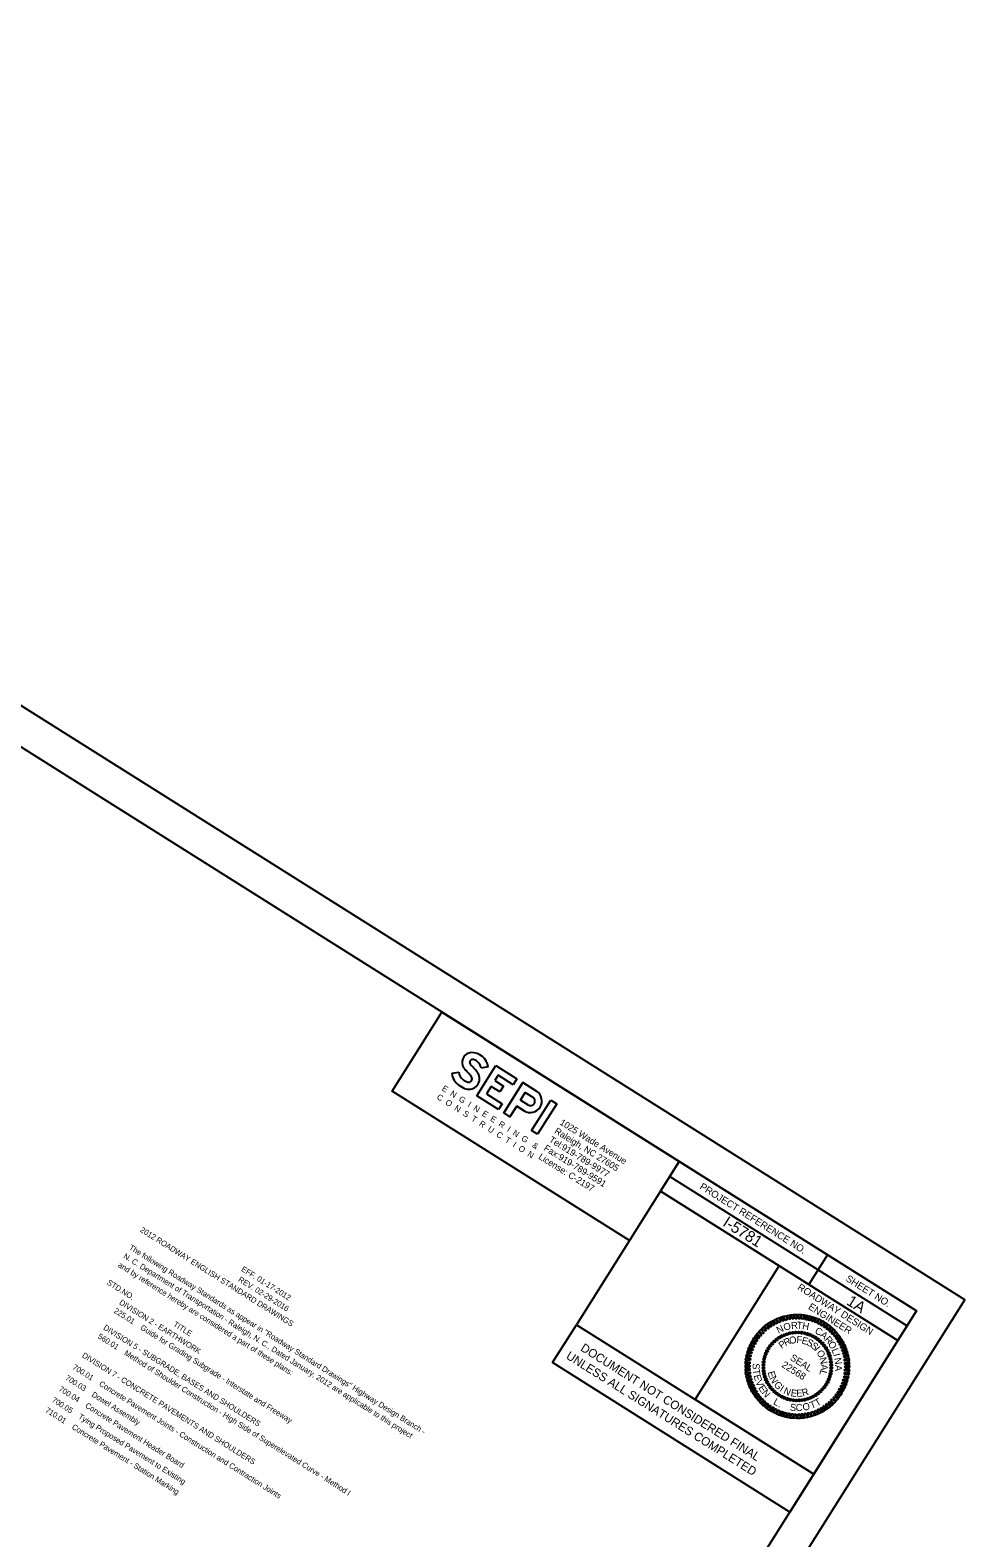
# Model space of a CAD drawing. Extents: x 2337281 to 2340318, y 809513 to 812268.
# Drawn here: x 2339318 to 2340318, y 810655 to 812268 of the extents above; entities that cross this region are included whole.
import ezdxf

# ---------------------------------------------------------------- set-up
doc = ezdxf.new("R2010")
doc.units = 0
for name, color, linetype in [('Default', 7, 'Continuous'), ('Old_Level_2', 7, 'Continuous'), ('Old_Level_58', 7, 'Continuous'), ('Old_Level_61', 7, 'Continuous'), ('Sheet Data Field CELL', 7, 'Continuous'), ('Sheet PE Seal Cell', 7, 'Continuous'), ('Sheet Plan And Profile CELL', 7, 'Continuous'), ('Sheet Plot Border Outside CELL', 7, 'Continuous'), ('Sheet Sticker Exception Certification CELL', 7, 'Continuous')]:
    doc.layers.add(name, color=color, linetype=linetype)

msp = doc.modelspace()

# ---------------------------------------------------------------- linework, layer by layer
at = {"layer": 'Old_Level_58'}
msp.add_lwpolyline([(2339758.7, 811217.1), (2340012.7, 811057.3), (2339959.4, 810972.6), (2339705.4, 811132.4)], close=True, dxfattribs=at)
at = {"layer": 'Old_Level_61'}
for p, q in [((2339769.5, 811151.6), (2339776.8, 811152.9)), ((2339796.1, 811127.4), (2339816.5, 811159.9)), ((2339808.3, 811158.6), (2339800.8, 811157)), ((2339819, 811149.5), (2339815.4, 811143.9)), ((2339816.5, 811159.9), (2339839, 811145.7)), ((2339835, 811139.3), (2339819, 811149.5)), ((2339811.5, 811137.6), (2339806.5, 811129.7)), ((2339820.8, 811131.7), (2339811.5, 811137.6)), ((2339815.4, 811143.9), (2339824.7, 811138)), ((2339824.7, 811138), (2339820.8, 811131.7)), ((2339839, 811145.7), (2339835, 811139.3)), ((2339860, 811132.5), (2339845.4, 811141.7)), ((2339819.3, 811112.8), (2339796.1, 811127.4)), ((2339806.5, 811129.7), (2339823.3, 811119.1)), ((2339823.3, 811119.1), (2339819.3, 811112.8)), ((2339850.8, 811117.8), (2339842.8, 811122.9)), ((2339854.7, 811090.5), (2339875.2, 811122.9)), ((2339881.6, 811118.9), (2339861.2, 811086.4)), ((2339875.2, 811122.9), (2339881.6, 811118.9)), ((2339861.2, 811086.4), (2339854.7, 811090.5))]:
    msp.add_line(p, q, dxfattribs=at)
for points in [[(2339846.8, 811111.5), (2339838.8, 811116.5), (2339831.6, 811105.1), (2339825, 811109.2), (2339845.4, 811141.7)], [(2339845.4, 811141.7), (2339825, 811109.2), (2339831.6, 811105.1), (2339838.8, 811116.5), (2339846.8, 811111.5)], [(2339842.8, 811122.9), (2339848, 811131.2), (2339856.1, 811126.2)], [(2339842.8, 811122.9), (2339848, 811131.2), (2339856.1, 811126.2)], [(2339845.4, 811141.7), (2339860, 811132.5)], [(2339850.8, 811117.8), (2339842.8, 811122.9)]]:
    msp.add_lwpolyline(points, dxfattribs=at)
for centre, radius, start, end in [((2339791, 811163.2), 10.6, 95.5503, 197.4787), ((2339791.7, 811163.3), 3.17, 71.3443, 183.3281), ((2339794.4, 811164.4), 6.07, 192.6469, 224.6621), ((2339790.3, 811155.4), 18.4, 9.946, 90.7914), ((2339789.3, 811155.1), 11.7, 9.434, 73.0111), ((2339786.2, 811152.9), 16.8, 184.1828, 236.8365), ((2339788.6, 811154.3), 11.9, 187.0277, 233.5862), ((2339795.3, 811165.8), 15.6, 201.8408, 225.1641), ((2339787.8, 811145.8), 11.3, 251.7121, 31.405), ((2339752.2, 811120.5), 47, 35.599, 46.8737), ((2339787.4, 811145.7), 3.69, 253.9268, 34.4617), ((2339754, 811121.2), 53.1, 35.0181, 47.1994), ((2339792.3, 811159.1), 25.4, 232.9472, 251.5878), ((2339790.8, 811156.4), 14.8, 231.6606, 252.8619), ((2339853.4, 811122), 12.4, 237.8219, 57.8219), ((2339853.4, 811122), 12.4, 237.8219, 57.8219), ((2339853.5, 811122), 4.93, 237.8219, 57.8219), ((2339853.5, 811122), 4.93, 237.8219, 57.8219)]:
    msp.add_arc(centre, radius, start, end, dxfattribs=at)
at = {"layer": 'Sheet PE Seal Cell'}
for points in [[(2340119.4, 810885), (2340117.3, 810889.2), (2340119.6, 810890.1), (2340121, 810885.6)], [(2340122.7, 810886.3), (2340120.9, 810890.6), (2340123.2, 810891.3), (2340124.3, 810886.8)], [(2340126.1, 810887.3), (2340124.6, 810891.7), (2340127, 810892.3), (2340127.8, 810887.7)], [(2340129.6, 810888.1), (2340128.4, 810892.6), (2340130.8, 810893), (2340131.3, 810888.4)], [(2340133.1, 810888.6), (2340132.3, 810893.2), (2340134.7, 810893.4), (2340134.8, 810888.8)], [(2340136.6, 810888.9), (2340136.1, 810893.6), (2340138.6, 810893.6), (2340138.3, 810889)], [(2340140.2, 810889), (2340140, 810893.6), (2340142.4, 810893.5), (2340141.9, 810888.9)], [(2340143.7, 810888.8), (2340143.9, 810893.4), (2340146.3, 810893.1), (2340145.4, 810888.6)], [(2340147.3, 810888.3), (2340147.8, 810893), (2340150.1, 810892.5), (2340149, 810888)], [(2340150.8, 810887.6), (2340151.6, 810892.2), (2340153.9, 810891.6), (2340152.4, 810887.2)], [(2340154.2, 810886.7), (2340155.3, 810891.2), (2340157.6, 810890.4), (2340155.8, 810886.2)], [(2340157.6, 810885.5), (2340159, 810890), (2340161.2, 810889), (2340159.2, 810884.9)], [(2340099.6, 810870.2), (2340095.8, 810873), (2340097.4, 810874.8), (2340100.7, 810871.5)], [(2340101.9, 810872.9), (2340098.4, 810875.9), (2340100.1, 810877.6), (2340103.1, 810874.1)], [(2340104.5, 810875.4), (2340101.1, 810878.7), (2340102.9, 810880.2), (2340105.7, 810876.6)], [(2340107.2, 810877.7), (2340104, 810881.2), (2340106, 810882.7), (2340108.5, 810878.8)], [(2340110, 810879.9), (2340107.1, 810883.5), (2340109.2, 810884.9), (2340111.4, 810880.8)], [(2340113, 810881.8), (2340110.4, 810885.7), (2340112.5, 810886.8), (2340114.5, 810882.7)], [(2340116.1, 810883.5), (2340113.8, 810887.6), (2340116, 810888.6), (2340117.7, 810884.3)], [(2340160.8, 810884.1), (2340162.6, 810888.5), (2340164.7, 810887.3), (2340162.4, 810883.4)], [(2340164, 810882.5), (2340166, 810886.7), (2340168.1, 810885.4), (2340165.5, 810881.6)], [(2340167, 810880.6), (2340169.4, 810884.7), (2340171.3, 810883.3), (2340168.5, 810879.7)], [(2340169.9, 810878.6), (2340172.6, 810882.5), (2340174.4, 810880.9), (2340171.3, 810877.5)], [(2340172.7, 810876.3), (2340175.6, 810880), (2340177.3, 810878.4), (2340174, 810875.2)], [(2340175.3, 810873.9), (2340178.4, 810877.4), (2340180.1, 810875.6), (2340176.5, 810872.7)], [(2340177.7, 810871.3), (2340181.1, 810874.5), (2340182.6, 810872.7), (2340178.8, 810870)], [(2340091, 810854.8), (2340086.5, 810856.1), (2340087.3, 810858.3), (2340091.5, 810856.4)], [(2340092.2, 810858.1), (2340087.8, 810859.7), (2340088.9, 810861.9), (2340092.9, 810859.7)], [(2340093.8, 810861.3), (2340089.5, 810863.2), (2340090.7, 810865.3), (2340094.6, 810862.8)], [(2340095.5, 810864.4), (2340091.4, 810866.6), (2340092.7, 810868.6), (2340096.4, 810865.9)], [(2340097.5, 810867.4), (2340093.5, 810869.9), (2340094.9, 810871.8), (2340098.5, 810868.8)], [(2340179.9, 810868.5), (2340183.5, 810871.5), (2340184.9, 810869.5), (2340181, 810867.1)], [(2340182, 810865.6), (2340185.7, 810868.3), (2340187, 810866.3), (2340182.9, 810864.1)], [(2340183.8, 810862.5), (2340187.8, 810865), (2340188.8, 810862.9), (2340184.6, 810861)], [(2340185.4, 810859.3), (2340189.5, 810861.6), (2340190.5, 810859.3), (2340186.1, 810857.8)], [(2340186.8, 810856.1), (2340191, 810858), (2340191.8, 810855.7), (2340187.4, 810854.5)], [(2340088.2, 810840.9), (2340083.5, 810840.8), (2340083.7, 810843.3), (2340088.3, 810842.6)], [(2340088.5, 810844.4), (2340083.8, 810844.7), (2340084.2, 810847.1), (2340088.8, 810846.1)], [(2340089.1, 810847.9), (2340084.5, 810848.5), (2340085, 810850.9), (2340089.4, 810849.6)], [(2340089.9, 810851.4), (2340085.3, 810852.3), (2340086, 810854.6), (2340090.4, 810853)], [(2340187.9, 810852.7), (2340192.3, 810854.3), (2340192.9, 810852), (2340188.4, 810851.1)], [(2340188.8, 810849.3), (2340193.3, 810850.6), (2340193.8, 810848.2), (2340189.2, 810847.6)], [(2340189.5, 810845.8), (2340194.1, 810846.7), (2340194.4, 810844.3), (2340189.7, 810844.1)], [(2340189.9, 810842.2), (2340194.5, 810842.9), (2340194.7, 810840.5), (2340190, 810840.5)], [(2340088.1, 810837.3), (2340083.5, 810837), (2340083.5, 810839.4), (2340088.1, 810839)], [(2340088.3, 810833.7), (2340083.7, 810833.1), (2340083.5, 810835.5), (2340088.2, 810835.4)], [(2340088.7, 810830.2), (2340084.1, 810829.2), (2340083.8, 810831.6), (2340088.5, 810831.9)], [(2340089.4, 810826.7), (2340084.9, 810825.4), (2340084.4, 810827.8), (2340089, 810828.4)], [(2340090.3, 810823.3), (2340085.9, 810821.7), (2340085.3, 810824), (2340089.8, 810824.9)], [(2340188.3, 810824.6), (2340192.9, 810823.6), (2340192.2, 810821.3), (2340187.8, 810822.9)], [(2340189.1, 810828.1), (2340193.7, 810827.4), (2340193.2, 810825.1), (2340188.8, 810826.4)], [(2340189.7, 810831.6), (2340194.4, 810831.3), (2340194, 810828.9), (2340189.4, 810829.9)], [(2340190, 810835.1), (2340194.7, 810835.1), (2340194.5, 810832.7), (2340189.9, 810833.4)], [(2340190.1, 810838.7), (2340194.8, 810839), (2340194.7, 810836.6), (2340190.1, 810837)], [(2340091.4, 810819.9), (2340087.2, 810818), (2340086.4, 810820.3), (2340090.8, 810821.5)], [(2340092.8, 810816.6), (2340088.7, 810814.4), (2340087.7, 810816.6), (2340092.1, 810818.2)], [(2340094.4, 810813.4), (2340090.4, 810810.9), (2340089.4, 810813.1), (2340093.6, 810815)], [(2340096.2, 810810.4), (2340092.5, 810807.6), (2340091.2, 810809.7), (2340095.3, 810811.8)], [(2340098.3, 810807.5), (2340094.7, 810804.4), (2340093.3, 810806.4), (2340097.2, 810808.8)], [(2340180.8, 810808.6), (2340184.7, 810806.1), (2340183.3, 810804.2), (2340179.7, 810807.2)], [(2340182.7, 810811.6), (2340186.8, 810809.4), (2340185.5, 810807.3), (2340181.8, 810810.1)], [(2340184.4, 810814.7), (2340188.7, 810812.8), (2340187.5, 810810.7), (2340183.6, 810813.1)], [(2340186, 810817.9), (2340190.4, 810816.3), (2340189.3, 810814.1), (2340185.3, 810816.3)], [(2340187.2, 810821.2), (2340191.7, 810819.9), (2340190.9, 810817.7), (2340186.7, 810819.6)], [(2340100.5, 810804.7), (2340097.1, 810801.4), (2340095.6, 810803.3), (2340099.4, 810806)], [(2340102.9, 810802.1), (2340099.8, 810798.6), (2340098.1, 810800.4), (2340101.7, 810803.3)], [(2340105.5, 810799.6), (2340102.6, 810795.9), (2340100.9, 810797.6), (2340104.2, 810800.8)], [(2340108.3, 810797.4), (2340105.6, 810793.5), (2340103.8, 810795), (2340106.9, 810798.4)], [(2340111.2, 810795.3), (2340108.8, 810791.3), (2340106.9, 810792.7), (2340109.7, 810796.3)], [(2340114.2, 810793.5), (2340112.2, 810789.3), (2340110.1, 810790.5), (2340112.7, 810794.3)], [(2340117.4, 810791.9), (2340115.6, 810787.5), (2340113.5, 810788.6), (2340115.8, 810792.6)], [(2340162.1, 810792.5), (2340164.4, 810788.4), (2340162.2, 810787.4), (2340160.5, 810791.7)], [(2340165.2, 810794.2), (2340167.8, 810790.3), (2340165.7, 810789.1), (2340163.7, 810793.3)], [(2340168.2, 810796.1), (2340171.1, 810792.4), (2340169, 810791.1), (2340166.8, 810795.1)], [(2340171, 810798.2), (2340174.2, 810794.8), (2340172.2, 810793.3), (2340169.7, 810797.2)], [(2340173.7, 810800.6), (2340177.1, 810797.3), (2340175.3, 810795.7), (2340172.5, 810799.4)], [(2340176.3, 810803.1), (2340179.8, 810800.1), (2340178.1, 810798.4), (2340175.1, 810801.8)], [(2340178.6, 810805.7), (2340182.4, 810803), (2340180.8, 810801.2), (2340177.5, 810804.4)], [(2340120.6, 810790.5), (2340119.2, 810786), (2340117, 810787), (2340119.1, 810791.1)], [(2340124, 810789.3), (2340122.9, 810784.7), (2340120.6, 810785.5), (2340122.4, 810789.8)], [(2340127.4, 810788.4), (2340126.6, 810783.7), (2340124.3, 810784.4), (2340125.8, 810788.8)], [(2340130.9, 810787.7), (2340130.5, 810783), (2340128.1, 810783.5), (2340129.2, 810787.9)], [(2340134.5, 810787.2), (2340134.3, 810782.5), (2340131.9, 810782.8), (2340132.8, 810787.4)], [(2340138, 810787), (2340138.2, 810782.3), (2340135.8, 810782.5), (2340136.3, 810787.1)], [(2340141.6, 810787.1), (2340142.1, 810782.4), (2340139.6, 810782.4), (2340139.9, 810787)], [(2340145.1, 810787.4), (2340145.9, 810782.7), (2340143.5, 810782.5), (2340143.4, 810787.2)], [(2340148.6, 810787.9), (2340149.8, 810783.4), (2340147.4, 810783), (2340146.9, 810787.6)], [(2340152.1, 810788.7), (2340153.6, 810784.2), (2340151.2, 810783.7), (2340150.4, 810788.3)], [(2340155.5, 810789.7), (2340157.3, 810785.4), (2340155, 810784.7), (2340153.9, 810789.2)], [(2340158.8, 810791), (2340160.9, 810786.8), (2340158.6, 810785.9), (2340157.3, 810790.3)]]:
    msp.add_lwpolyline(points, close=True, dxfattribs=at)
for centre, radius in [((2340128, 810872.6), 1.13), ((2340131, 810873.5), 1.12), ((2340134.2, 810874), 1.12), ((2340137.3, 810874.3), 1.12), ((2340140.5, 810874.3), 1.12), ((2340143.7, 810874.1), 1.12), ((2340146.8, 810873.5), 1.12), ((2340149.8, 810872.7), 1.12), ((2340152.8, 810871.7), 1.12), ((2340108.3, 810857.4), 1.13), ((2340110.1, 810860), 1.13), ((2340112.1, 810862.4), 1.13), ((2340114.4, 810864.7), 1.13), ((2340116.8, 810866.7), 1.12), ((2340119.4, 810868.6), 1.12), ((2340122.1, 810870.2), 1.13), ((2340125, 810871.5), 1.12), ((2340155.7, 810870.3), 1.12), ((2340158.5, 810868.8), 1.12), ((2340161.1, 810867), 1.12), ((2340163.5, 810864.9), 1.12), ((2340165.8, 810862.7), 1.12), ((2340167.8, 810860.3), 1.12), ((2340169.7, 810857.7), 1.12), ((2340102.8, 810839.4), 1.12), ((2340103, 810842.5), 1.12), ((2340103.5, 810845.7), 1.12), ((2340104.3, 810848.7), 1.13), ((2340105.4, 810851.7), 1.13), ((2340106.7, 810854.6), 1.13), ((2340171.3, 810855), 1.12), ((2340172.6, 810852.1), 1.12), ((2340173.7, 810849.1), 1.12), ((2340174.6, 810846.1), 1.12), ((2340175.1, 810842.9), 1.12), ((2340175.4, 810839.8), 1.12), ((2340102.8, 810836.2), 1.12), ((2340103.1, 810833), 1.12), ((2340103.6, 810829.9), 1.13), ((2340104.5, 810826.9), 1.12), ((2340105.6, 810823.9), 1.12), ((2340172.8, 810824.2), 1.13), ((2340173.9, 810827.2), 1.13), ((2340174.7, 810830.3), 1.12), ((2340175.2, 810833.4), 1.12), ((2340175.4, 810836.6), 1.12), ((2340106.9, 810821), 1.12), ((2340108.5, 810818.3), 1.12), ((2340110.4, 810815.7), 1.12), ((2340112.4, 810813.3), 1.12), ((2340114.7, 810811), 1.12), ((2340117.1, 810809), 1.12), ((2340119.7, 810807.2), 1.12), ((2340158.8, 810807.4), 1.13), ((2340161.4, 810809.2), 1.12), ((2340163.8, 810811.3), 1.13), ((2340166.1, 810813.6), 1.13), ((2340168.1, 810816), 1.13), ((2340169.9, 810818.6), 1.13), ((2340171.5, 810821.4), 1.13), ((2340122.5, 810805.6), 1.12), ((2340125.4, 810804.3), 1.12), ((2340128.4, 810803.2), 1.12), ((2340131.4, 810802.4), 1.12), ((2340134.6, 810801.9), 1.12), ((2340137.7, 810801.6), 1.12), ((2340140.9, 810801.7), 1.12), ((2340144, 810801.9), 1.12), ((2340147.2, 810802.5), 1.12), ((2340150.2, 810803.4), 1.12), ((2340153.2, 810804.5), 1.12), ((2340156.1, 810805.8), 1.12)]:
    msp.add_circle(centre, radius, dxfattribs=at)
at = {"layer": 'Sheet Plan And Profile CELL'}
for p, q in [((2340002.6, 811041.3), (2340256.6, 810881.5)), ((2339992.6, 811025.5), (2339902.8, 810882.6)), ((2339992.6, 811025.5), (2340246.6, 810865.6)), ((2340171.4, 810957.3), (2340151.4, 810925.5))]:
    msp.add_line(p, q, dxfattribs=at)
for points in [[(2340266.6, 810897.4), (2338362.4, 812095.9), (2337523.4, 810763), (2339427.7, 809564.5)], [(2340012.7, 811057.3), (2340266.6, 810897.4), (2340246.6, 810865.6), (2339992.6, 811025.5)], [(2340119.7, 810945.5), (2340246.6, 810865.6), (2340156.7, 810722.8), (2340029.8, 810802.7)]]:
    msp.add_lwpolyline(points, close=True, dxfattribs=at)
at = {"layer": 'Sheet Plot Border Outside CELL'}
msp.add_lwpolyline([(2337281.3, 810871.1), (2339439.4, 809512.8), (2340318.3, 810909.2), (2338160.2, 812267.5)], close=True, dxfattribs=at)
at = {"layer": 'Sheet Sticker Exception Certification CELL'}
for p, q in [((2339877.2, 810842.1), (2339902.8, 810882.6)), ((2339902.8, 810882.6), (2340156.7, 810722.8)), ((2340131.2, 810682.2), (2339877.2, 810842.1)), ((2340156.7, 810722.8), (2340131.2, 810682.2))]:
    msp.add_line(p, q, dxfattribs=at)

# ---------------------------------------------------------------- texts
at = {"layer": 'Default'}
for s, p in [('2012 ROADWAY ENGLISH STANDARD DRAWINGS', (2339435.3, 810982.5)), ('N. C. Department of Transportation - Raleigh, N. C., Dated January, 2012 are applicable to this project', (2339417.5, 810954.4)), ('The following Roadway Standards as appear in "Roadway Standard Drawings" Highway Design Branch -', (2339423.4, 810963.7)), ('and by reference hereby are considered a part of these plans:', (2339411.6, 810945)), ('                                                      EFF. 01-17-2012', (2339441.6, 811004.7)), ('STD.NO.                       TITLE', (2339399.8, 810926.2)), ('                                                      REV. 02-29-2016', (2339438.4, 810993.6)), ('DIVISION 2 - EARTHWORK', (2339412.9, 810904.9)), ('225.01    Guide for Grading Subgrade - Interstate and Freeway', (2339407.2, 810895.9)), ('560.01    Method of Shoulder Construction - High Side of Superelevated Curve - Method I', (2339390, 810868.6)), ('DIVISION 5 - SUBGRADE, BASES AND SHOULDERS', (2339395.9, 810878)), ('700.01    Concrete Pavement Joints - Construction and Contraction Joints ', (2339363, 810835.7)), ('DIVISION 7 - CONCRETE PAVEMENTS AND SHOULDERS', (2339373.1, 810848.3)), ('700.03    Dowel Assembly', (2339355.1, 810824.2)), ('700.04    Concrete Pavement Header Board', (2339348.2, 810812.4)), ('710.01    Concrete Pavement - Station Marking', (2339333.8, 810789.6)), ('700.05    Tying Proposed Pavement to Existing', (2339340.8, 810800.6))]:
    msp.add_text(s, height=6, rotation=327.8134, dxfattribs=at).set_placement(p)
at = {"layer": 'Old_Level_2'}
for s, height, rotation, p in [('E  N  G  I  N  E  E  R  I  N  G   &', 6.375, 327.8219, (2339758.1, 811133.8)), ('C  O  N  S  T  R  U  C  T  I  O  N', 6.375, 327.8219, (2339752.6, 811124.6)), ('1025 Wade Avenue', 6.986, 328.1613, (2339884.2, 811097.2)), ('Tel:919-789-9977 ', 6.986, 328.1613, (2339872.8, 811078.8)), ('Raleigh, NC 27605', 6.986, 328.1613, (2339878.5, 811088)), ('Fax:919-789-9591', 6.986, 328.1613, (2339867.1, 811069.7)), ('License: C-2197', 6.986, 328.1613, (2339861.4, 811060.5))]:
    msp.add_text(s, height=height, rotation=rotation, dxfattribs=at).set_placement(p)
at = {"layer": 'Sheet Data Field CELL'}
for s, p in [('I-5781', (2340058.4, 810989.1)), ('1A', (2340190.8, 810904.9))]:
    msp.add_text(s, height=12, rotation=327.8134, dxfattribs=at).set_placement(p)
at = {"layer": 'Sheet PE Seal Cell'}
for s, rotation, p in [('N', 26.348, (2340118.9, 810872.9)), ('O', 16.1375, (2340125.4, 810876)), ('R', 5.4124, (2340132.7, 810877.9)), ('T', 357.2037, (2340138.4, 810878.4)), ('H', 349.4145, (2340143.9, 810878.1)), ('C', 329.7753, (2340157.1, 810874.1)), ('A', 320.2702, (2340162.8, 810870.7)), ('P', 36.1478, (2340122.3, 810856.6)), ('R', 24.3856, (2340126.4, 810859.6)), ('O', 12.2861, (2340131.2, 810861.8)), ('F', 356.4773, (2340138, 810863)), ('E', 344.7994, (2340143.1, 810862.7)), ('S', 333.0371, (2340148.1, 810861.4)), ('S', 321.0782, (2340152.7, 810859)), ('I', 309.1192, (2340156.8, 810855.8)), ('R', 311.2227, (2340167.7, 810866.5)), ('O', 303.0141, (2340171.5, 810862.1)), ('L', 292.2889, (2340175.4, 810855.7)), ('S', 269.9848, (2340091.3, 810841.4)), ('22568', 327.8134, (2340121.6, 810837.9)), ('SEAL', 327.8134, (2340130.6, 810845.5)), ('O', 300.3638, (2340159.3, 810852.9)), ('N', 284.555, (2340162.6, 810846.8)), ('I', 284.8238, (2340177.4, 810850.8)), ('N', 278.8838, (2340178.5, 810846.8)), ('T', 278.0981, (2340091.3, 810834.6)), ('E', 285.8873, (2340092.2, 810828.2)), ('V', 293.8672, (2340094, 810821.7)), ('E', 285.6641, (2340107.2, 810831.8)), ('N', 297.4263, (2340109.1, 810825.4)), ('L', 256.1691, (2340163.9, 810834.6)), ('A', 269.505, (2340164.1, 810840.4)), ('A', 268.6734, (2340179.5, 810839.7)), ('E', 302.5525, (2340097, 810815.1)), ('N', 310.5324, (2340100.6, 810809.5)), ('G', 312.4764, (2340113.4, 810818)), ('I', 327.5264, (2340119.5, 810812)), ('N', 336.2818, (2340123.6, 810809.3)), ('E', 351.3319, (2340131.6, 810806.3)), ('E', 3.0941, (2340138.2, 810805.5)), ('R', 14.8564, (2340144.9, 810806)), ('L', 330.6291, (2340112.7, 810798)), ('.', 338.0942, (2340118.1, 810794.9)), ('S', 354.0635, (2340130.8, 810790.8)), ('C', 2.1769, (2340137.5, 810790.1)), ('O', 11.6819, (2340145.5, 810790.5)), ('T', 22.4071, (2340154.2, 810792.5)), ('T', 30.1963, (2340160.2, 810795))]:
    msp.add_text(s, height=7.5, rotation=rotation, dxfattribs=at).set_placement(p)
at = {"layer": 'Sheet Plan And Profile CELL'}
for s, p in [('PROJECT REFERENCE NO.', (2340033.9, 811028.5)), ('ROADWAY DESIGN', (2340138.5, 810920.8)), ('SHEET NO.', (2340190.2, 810930)), ('ENGINEER', (2340150.1, 810900))]:
    msp.add_text(s, height=7.5, rotation=327.8134, dxfattribs=at).set_placement(p)
at = {"layer": 'Sheet Sticker Exception Certification CELL'}
for s, p in [('DOCUMENT NOT CONSIDERED FINAL', (2339906.3, 810855.5)), ('UNLESS ALL SIGNATURES COMPLETED', (2339890.8, 810847))]:
    msp.add_text(s, height=9.186, rotation=327.8134, dxfattribs=at).set_placement(p)

doc.saveas('drawing.dxf')
